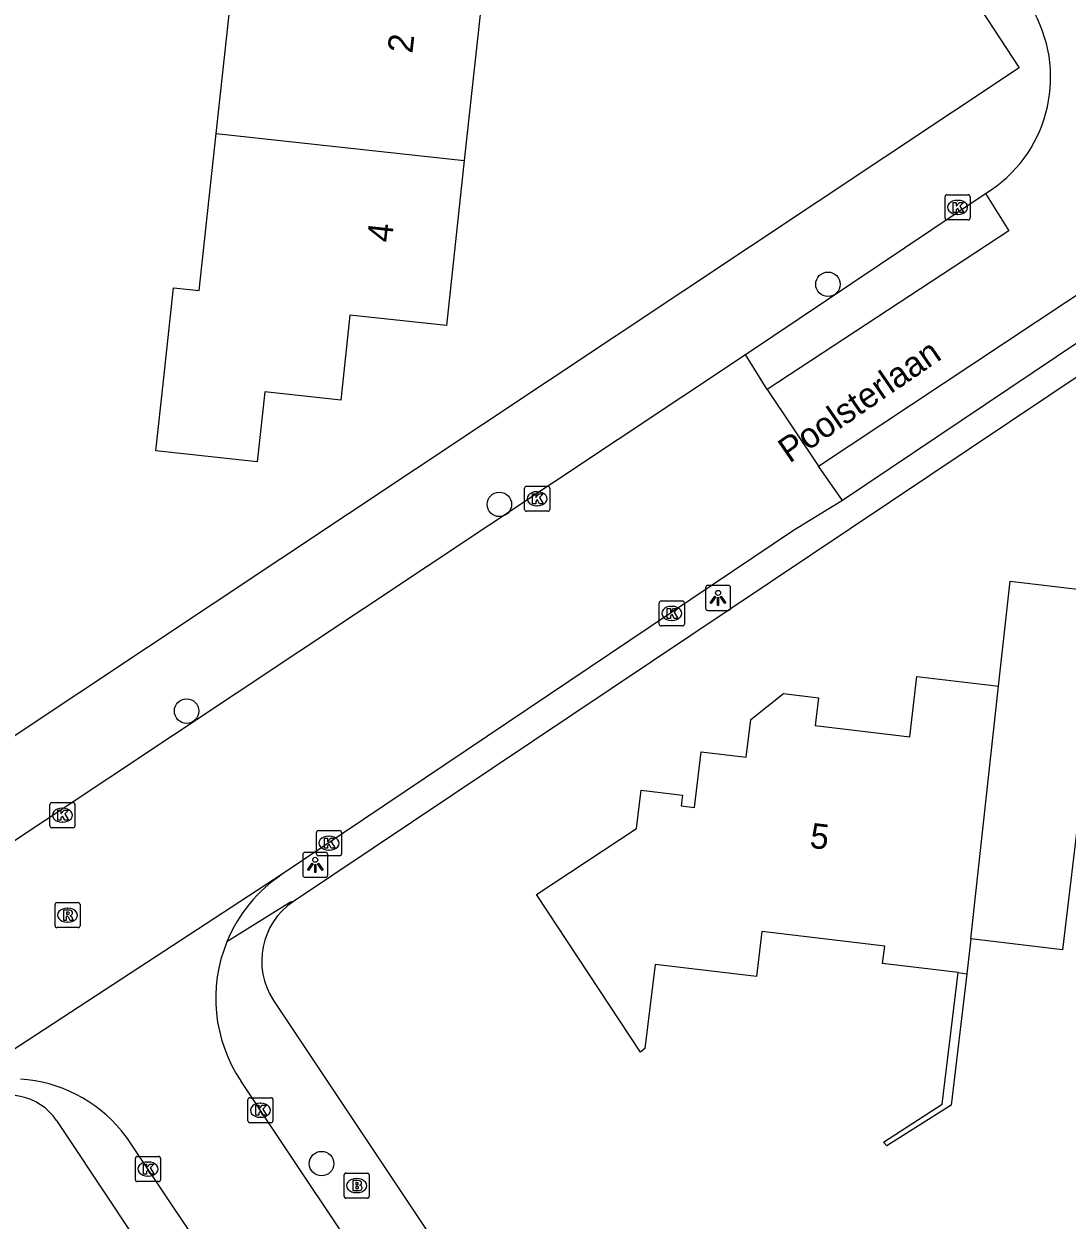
# Model space of a CAD drawing. Extents: x 162398 to 163643, y 386453 to 387397.
# Drawn here: x 163055.23 to 163096.85, y 386746.74 to 386794.48 of the extents above; entities that cross this region are included whole.
import ezdxf

# ---------------------------------------------------------------- set-up
doc = ezdxf.new("R2010")
doc.units = 0
for name, color, linetype in [('IMGEO_Boom', 7, 'Continuous'), ('IMGEO_Brandkraan', 7, 'Continuous'), ('IMGEO_Kolk', 7, 'Continuous'), ('IMGEO_Lichtpunt', 7, 'Continuous'), ('IMGEO_Muur', 7, 'Continuous'), ('IMGEO_Openbare_ruimte_label', 7, 'Continuous'), ('IMGEO_Pand', 7, 'Continuous'), ('IMGEO_Pand_nummerreeks', 7, 'Continuous'), ('IMGEO_Rijbaan_lokaal_gesloten', 7, 'Continuous'), ('IMGEO_Rijbaan_lokaal_open', 7, 'Continuous'), ('IMGEO_Rioolput', 7, 'Continuous'), ('IMGEO_Voetpad_open', 7, 'Continuous')]:
    doc.layers.add(name, color=color, linetype=linetype)

msp = doc.modelspace()

# ---------------------------------------------------------------- linework, layer by layer
at = {"layer": 'IMGEO_Boom'}
for centre in [(163087.31, 386784.089), (163074.198, 386775.307), (163061.721, 386767.055), (163067.103, 386748.994)]:
    msp.add_circle(centre, 0.489, dxfattribs=at)
at = {"layer": 'IMGEO_Brandkraan'}
for p, q in [((163068.004, 386747.688), (163068.004, 386748.54)), ((163068.079, 386748.614), (163068.931, 386748.614)), ((163068.492, 386748.394), (163068.517, 386748.394)), ((163069.005, 386748.54), (163069.005, 386747.688)), ((163068.515, 386747.834), (163068.49, 386747.834)), ((163068.931, 386747.614), (163068.079, 386747.614))]:
    msp.add_line(p, q, dxfattribs=at)
for points in [[(163068.004, 386747.688), (163068.004, 386748.54)], [(163068.079, 386748.614), (163068.931, 386748.614)], [(163068.352, 386748.314), (163068.352, 386747.914), (163068.565, 386747.914)], [(163068.583, 386748.314), (163068.352, 386748.314)], [(163068.531, 386748.233), (163068.477, 386748.233), (163068.477, 386748.157)], [(163069.005, 386748.54), (163069.005, 386747.688)], [(163068.477, 386748.157), (163068.53, 386748.157)], [(163068.539, 386748.081), (163068.477, 386748.081), (163068.477, 386748)], [(163068.477, 386748), (163068.539, 386748)], [(163068.931, 386747.614), (163068.079, 386747.614)]]:
    msp.add_lwpolyline(points, dxfattribs=at)
for centre, radius, start, end in [((163068.081, 386748.538), 0.0765, 91.552, 178.448), ((163068.081, 386748.538), 0.0765, 91.552, 178.448), ((163068.532, 386748.195), 0.0379, 267.8285, 90.9355), ((163068.587, 386748.169), 0.145, 59.4692, 91.5367), ((163068.612, 386748.216), 0.0922, 285.5137, 58.1501), ((163068.929, 386748.538), 0.0765, 1.552, 88.448), ((163068.929, 386748.538), 0.0765, 1.552, 88.448), ((163068.54, 386748.04), 0.0404, 269.8759, 90.5077), ((163068.571, 386748.165), 0.251, 268.6676, 293.5347), ((163068.617, 386748.024), 0.105, 301.3115, 78.989), ((163068.081, 386747.69), 0.0765, 181.552, 268.448), ((163068.081, 386747.69), 0.0765, 181.552, 268.448), ((163068.929, 386747.69), 0.0765, 271.552, 358.448), ((163068.929, 386747.69), 0.0765, 271.552, 358.448)]:
    msp.add_arc(centre, radius, start, end, dxfattribs=at)
for centre, major_axis, ratio, start_param, end_param in [((163068.491, 386748.114), (-0.387, 0.002), 0.722429, 4.712389, 7.853982), ((163068.516, 386748.114), (-0.39, 0.002), 0.717154, 1.570796, 4.712389)]:
    msp.add_ellipse(centre, major_axis=major_axis, ratio=ratio, start_param=start_param, end_param=end_param, dxfattribs=at)
at = {"layer": 'IMGEO_Kolk'}
for p, q in [((163091.982, 386786.735), (163091.982, 386787.587)), ((163092.057, 386787.661), (163092.909, 386787.661)), ((163092.47, 386787.441), (163092.495, 386787.441)), ((163092.983, 386787.587), (163092.983, 386786.735)), ((163092.909, 386786.661), (163092.057, 386786.661)), ((163092.493, 386786.881), (163092.468, 386786.881)), ((163075.205, 386775.104), (163075.205, 386775.956)), ((163075.28, 386776.03), (163076.132, 386776.03)), ((163076.206, 386775.956), (163076.206, 386775.104)), ((163075.693, 386775.81), (163075.718, 386775.81)), ((163076.132, 386775.03), (163075.28, 386775.03)), ((163075.716, 386775.25), (163075.691, 386775.25)), ((163080.579, 386770.528), (163080.579, 386771.38)), ((163080.654, 386771.454), (163081.506, 386771.454)), ((163081.067, 386771.234), (163081.092, 386771.234)), ((163081.58, 386771.38), (163081.58, 386770.528)), ((163081.09, 386770.674), (163081.065, 386770.674)), ((163081.506, 386770.454), (163080.654, 386770.454)), ((163056.264, 386762.476), (163056.264, 386763.328)), ((163056.339, 386763.402), (163057.191, 386763.402)), ((163056.752, 386763.182), (163056.777, 386763.182)), ((163057.265, 386763.328), (163057.265, 386762.476)), ((163056.775, 386762.622), (163056.75, 386762.622)), ((163057.191, 386762.402), (163056.339, 386762.402)), ((163066.901, 386761.357), (163066.901, 386762.209)), ((163066.976, 386762.283), (163067.828, 386762.283)), ((163067.902, 386762.209), (163067.902, 386761.357)), ((163067.389, 386762.063), (163067.414, 386762.063)), ((163067.828, 386761.283), (163066.976, 386761.283)), ((163067.412, 386761.503), (163067.387, 386761.503)), ((163064.239, 386751.623), (163065.091, 386751.623)), ((163064.164, 386750.697), (163064.164, 386751.549)), ((163064.652, 386751.403), (163064.677, 386751.403)), ((163065.165, 386751.549), (163065.165, 386750.697)), ((163065.091, 386750.623), (163064.239, 386750.623)), ((163064.675, 386750.843), (163064.65, 386750.843)), ((163059.677, 386748.351), (163059.677, 386749.203)), ((163059.752, 386749.277), (163060.604, 386749.277)), ((163060.678, 386749.203), (163060.678, 386748.351)), ((163060.165, 386749.057), (163060.19, 386749.057)), ((163060.604, 386748.277), (163059.752, 386748.277)), ((163060.188, 386748.497), (163060.163, 386748.497))]:
    msp.add_line(p, q, dxfattribs=at)
for points in [[(163091.982, 386786.735), (163091.982, 386787.587)], [(163092.057, 386787.661), (163092.909, 386787.661)], [(163092.983, 386787.587), (163092.983, 386786.735)], [(163092.303, 386787.361), (163092.426, 386787.361), (163092.426, 386787.21), (163092.556, 386787.361), (163092.72, 386787.361), (163092.574, 386787.21), (163092.727, 386786.961), (163092.575, 386786.961), (163092.49, 386787.125), (163092.426, 386787.058), (163092.426, 386786.961), (163092.303, 386786.961), (163092.303, 386787.361)], [(163092.909, 386786.661), (163092.057, 386786.661)], [(163075.205, 386775.104), (163075.205, 386775.956)], [(163075.28, 386776.03), (163076.132, 386776.03)], [(163076.206, 386775.956), (163076.206, 386775.104)], [(163075.526, 386775.73), (163075.649, 386775.73), (163075.649, 386775.579), (163075.779, 386775.73), (163075.943, 386775.73), (163075.797, 386775.579), (163075.95, 386775.33), (163075.798, 386775.33), (163075.713, 386775.494), (163075.649, 386775.427), (163075.649, 386775.33), (163075.526, 386775.33), (163075.526, 386775.73)], [(163076.132, 386775.03), (163075.28, 386775.03)], [(163080.579, 386770.528), (163080.579, 386771.38)], [(163080.654, 386771.454), (163081.506, 386771.454)], [(163080.9, 386771.154), (163081.023, 386771.154), (163081.023, 386771.003), (163081.153, 386771.154), (163081.317, 386771.154), (163081.171, 386771.003), (163081.324, 386770.754), (163081.172, 386770.754), (163081.087, 386770.918), (163081.023, 386770.851), (163081.023, 386770.754), (163080.9, 386770.754), (163080.9, 386771.154)], [(163081.58, 386771.38), (163081.58, 386770.528)], [(163081.506, 386770.454), (163080.654, 386770.454)], [(163056.264, 386762.476), (163056.264, 386763.328)], [(163056.339, 386763.402), (163057.191, 386763.402)], [(163056.585, 386763.102), (163056.708, 386763.102), (163056.708, 386762.951), (163056.838, 386763.102), (163057.002, 386763.102), (163056.856, 386762.951), (163057.009, 386762.702), (163056.857, 386762.702), (163056.772, 386762.866), (163056.708, 386762.799), (163056.708, 386762.702), (163056.585, 386762.702), (163056.585, 386763.102)], [(163057.265, 386763.328), (163057.265, 386762.476)], [(163057.191, 386762.402), (163056.339, 386762.402)], [(163066.901, 386761.357), (163066.901, 386762.209)], [(163066.976, 386762.283), (163067.828, 386762.283)], [(163067.902, 386762.209), (163067.902, 386761.357)], [(163067.222, 386761.983), (163067.345, 386761.983), (163067.345, 386761.832), (163067.475, 386761.983), (163067.639, 386761.983), (163067.493, 386761.832), (163067.646, 386761.583), (163067.494, 386761.583), (163067.409, 386761.747), (163067.345, 386761.68), (163067.345, 386761.583), (163067.222, 386761.583), (163067.222, 386761.983)], [(163067.828, 386761.283), (163066.976, 386761.283)], [(163064.239, 386751.623), (163065.091, 386751.623)], [(163064.164, 386750.697), (163064.164, 386751.549)], [(163064.485, 386751.323), (163064.608, 386751.323), (163064.608, 386751.172), (163064.738, 386751.323), (163064.902, 386751.323), (163064.756, 386751.172), (163064.909, 386750.923), (163064.757, 386750.923), (163064.672, 386751.087), (163064.608, 386751.02), (163064.608, 386750.923), (163064.485, 386750.923), (163064.485, 386751.323)], [(163065.165, 386751.549), (163065.165, 386750.697)], [(163065.091, 386750.623), (163064.239, 386750.623)], [(163059.677, 386748.351), (163059.677, 386749.203)], [(163059.752, 386749.277), (163060.604, 386749.277)], [(163060.678, 386749.203), (163060.678, 386748.351)], [(163059.998, 386748.977), (163060.121, 386748.977), (163060.121, 386748.826), (163060.251, 386748.977), (163060.415, 386748.977), (163060.269, 386748.826), (163060.422, 386748.577), (163060.27, 386748.577), (163060.185, 386748.741), (163060.121, 386748.674), (163060.121, 386748.577), (163059.998, 386748.577), (163059.998, 386748.977)], [(163060.604, 386748.277), (163059.752, 386748.277)]]:
    msp.add_lwpolyline(points, dxfattribs=at)
for centre, start, end in [((163092.059, 386787.585), 91.552, 178.448), ((163092.059, 386787.585), 91.552, 178.448), ((163092.907, 386787.585), 1.552, 88.448), ((163092.907, 386787.585), 1.552, 88.448), ((163092.059, 386786.737), 181.552, 268.448), ((163092.059, 386786.737), 181.552, 268.448), ((163092.907, 386786.737), 271.552, 358.448), ((163092.907, 386786.737), 271.552, 358.448), ((163075.282, 386775.954), 91.552, 178.448), ((163075.282, 386775.954), 91.552, 178.448), ((163076.13, 386775.954), 1.552, 88.448), ((163076.13, 386775.954), 1.552, 88.448), ((163075.282, 386775.106), 181.552, 268.448), ((163075.282, 386775.106), 181.552, 268.448), ((163076.13, 386775.106), 271.552, 358.448), ((163076.13, 386775.106), 271.552, 358.448), ((163080.656, 386771.378), 91.552, 178.448), ((163080.656, 386771.378), 91.552, 178.448), ((163081.504, 386771.378), 1.552, 88.448), ((163081.504, 386771.378), 1.552, 88.448), ((163080.656, 386770.53), 181.552, 268.448), ((163080.656, 386770.53), 181.552, 268.448), ((163081.504, 386770.53), 271.552, 358.448), ((163081.504, 386770.53), 271.552, 358.448), ((163056.341, 386763.326), 91.552, 178.448), ((163056.341, 386763.326), 91.552, 178.448), ((163057.189, 386763.326), 1.552, 88.448), ((163057.189, 386763.326), 1.552, 88.448), ((163056.341, 386762.478), 181.552, 268.448), ((163056.341, 386762.478), 181.552, 268.448), ((163057.189, 386762.478), 271.552, 358.448), ((163057.189, 386762.478), 271.552, 358.448), ((163066.978, 386762.207), 91.552, 178.448), ((163066.978, 386762.207), 91.552, 178.448), ((163067.826, 386762.207), 1.552, 88.448), ((163067.826, 386762.207), 1.552, 88.448), ((163066.978, 386761.359), 181.552, 268.448), ((163066.978, 386761.359), 181.552, 268.448), ((163067.826, 386761.359), 271.552, 358.448), ((163067.826, 386761.359), 271.552, 358.448), ((163064.241, 386751.547), 91.552, 178.448), ((163064.241, 386751.547), 91.552, 178.448), ((163065.089, 386751.547), 1.552, 88.448), ((163065.089, 386751.547), 1.552, 88.448), ((163064.241, 386750.699), 181.552, 268.448), ((163064.241, 386750.699), 181.552, 268.448), ((163065.089, 386750.699), 271.552, 358.448), ((163065.089, 386750.699), 271.552, 358.448), ((163059.754, 386749.201), 91.552, 178.448), ((163059.754, 386749.201), 91.552, 178.448), ((163060.602, 386749.201), 1.552, 88.448), ((163060.602, 386749.201), 1.552, 88.448), ((163059.754, 386748.353), 181.552, 268.448), ((163059.754, 386748.353), 181.552, 268.448), ((163060.602, 386748.353), 271.552, 358.448), ((163060.602, 386748.353), 271.552, 358.448)]:
    msp.add_arc(centre, 0.0765, start, end, dxfattribs=at)
for centre, major_axis, ratio, start_param, end_param in [((163092.469, 386787.161), (-0.387, 0.002), 0.722429, 4.712389, 7.853982), ((163092.494, 386787.161), (-0.39, 0.002), 0.717154, 1.570796, 4.712389), ((163075.692, 386775.53), (-0.387, 0.002), 0.722429, 4.712389, 7.853982), ((163075.717, 386775.53), (-0.39, 0.002), 0.717154, 1.570796, 4.712389), ((163081.066, 386770.954), (-0.387, 0.002), 0.722429, 4.712389, 7.853982), ((163081.091, 386770.954), (-0.39, 0.002), 0.717154, 1.570796, 4.712389), ((163056.751, 386762.902), (-0.387, 0.002), 0.722429, 4.712389, 7.853982), ((163056.776, 386762.902), (-0.39, 0.002), 0.717154, 1.570796, 4.712389), ((163067.388, 386761.783), (-0.387, 0.002), 0.722429, 4.712389, 7.853982), ((163067.413, 386761.783), (-0.39, 0.002), 0.717154, 1.570796, 4.712389), ((163064.651, 386751.123), (-0.387, 0.002), 0.722429, 4.712389, 7.853982), ((163064.676, 386751.123), (-0.39, 0.002), 0.717154, 1.570796, 4.712389), ((163060.164, 386748.777), (-0.387, 0.002), 0.722429, 4.712389, 7.853982), ((163060.189, 386748.777), (-0.39, 0.002), 0.717154, 1.570796, 4.712389)]:
    msp.add_ellipse(centre, major_axis=major_axis, ratio=ratio, start_param=start_param, end_param=end_param, dxfattribs=at)
at = {"layer": 'IMGEO_Lichtpunt'}
for p, q in [((163082.426, 386771.976), (163082.426, 386771.169)), ((163082.426, 386771.976), (163082.426, 386771.169)), ((163083.328, 386772.071), (163082.52, 386772.071)), ((163083.328, 386772.071), (163082.52, 386772.071)), ((163083.422, 386771.169), (163083.422, 386771.976)), ((163083.422, 386771.169), (163083.422, 386771.976)), ((163082.52, 386771.075), (163083.328, 386771.075)), ((163082.52, 386771.075), (163083.328, 386771.075)), ((163066.354, 386761.321), (163066.354, 386760.514)), ((163066.354, 386761.321), (163066.354, 386760.514)), ((163067.256, 386761.416), (163066.448, 386761.416)), ((163067.256, 386761.416), (163066.448, 386761.416)), ((163067.35, 386760.514), (163067.35, 386761.321)), ((163067.35, 386760.514), (163067.35, 386761.321)), ((163066.448, 386760.42), (163067.256, 386760.42)), ((163066.448, 386760.42), (163067.256, 386760.42))]:
    msp.add_line(p, q, dxfattribs=at)
for points in [[(163082.8, 386771.64), (163082.839, 386771.612), (163082.651, 386771.35), (163082.613, 386771.377), (163082.8, 386771.64)], [(163083.012, 386771.612), (163083.05, 386771.639), (163083.237, 386771.377), (163083.198, 386771.349), (163083.012, 386771.612)], [(163082.902, 386771.592), (163082.949, 386771.592), (163082.949, 386771.27), (163082.902, 386771.27), (163082.902, 386771.592)], [(163066.728, 386760.985), (163066.767, 386760.957), (163066.579, 386760.695), (163066.541, 386760.722), (163066.728, 386760.985)], [(163066.83, 386760.937), (163066.877, 386760.937), (163066.877, 386760.615), (163066.83, 386760.615), (163066.83, 386760.937)], [(163066.94, 386760.957), (163066.978, 386760.984), (163067.165, 386760.722), (163067.126, 386760.694), (163066.94, 386760.957)]]:
    msp.add_lwpolyline(points, dxfattribs=at)
for centre in [(163082.925, 386771.774), (163066.853, 386761.119)]:
    msp.add_circle(centre, 0.0994, dxfattribs=at)
for centre, start, end in [((163082.52, 386771.976), 90, 180), ((163082.52, 386771.976), 90, 180), ((163083.328, 386771.976), 0, 90), ((163083.328, 386771.976), 0, 90), ((163082.52, 386771.169), 180, 270), ((163082.52, 386771.169), 180, 270), ((163083.328, 386771.169), 270, 0), ((163083.328, 386771.169), 270, 360), ((163066.448, 386761.321), 90, 180), ((163066.448, 386761.321), 90, 180), ((163067.256, 386761.321), 0, 90), ((163067.256, 386761.321), 0, 90), ((163066.448, 386760.514), 180, 270), ((163066.448, 386760.514), 180, 270), ((163067.256, 386760.514), 270, 0), ((163067.256, 386760.514), 270, 360)]:
    msp.add_arc(centre, 0.0946, start, end, dxfattribs=at)
at = {"layer": 'IMGEO_Muur'}
msp.add_lwpolyline([(163092.848, 386756.574), (163092.221, 386751.327), (163089.656, 386749.699), (163089.531, 386749.856), (163091.873, 386751.371), (163092.499, 386756.616)], dxfattribs=at)
at = {"layer": 'IMGEO_Pand'}
for points in [[(163062.9, 386790.106), (163063.658, 386797.073), (163062.183, 386797.234), (163062.587, 386800.949), (163065.941, 386800.584), (163071.468, 386799.982), (163071.59, 386801.104), (163073.363, 386800.911), (163078.333, 386800.37), (163077.975, 386797.081), (163073.726, 386797.543), (163072.8, 386789.031)], [(163072.8, 386789.031), (163072.083, 386782.446), (163068.239, 386782.864), (163067.869, 386779.463), (163064.845, 386779.792), (163064.541, 386777.006), (163060.493, 386777.447), (163060.796, 386780.233), (163061.201, 386783.951), (163062.218, 386783.841), (163062.9, 386790.106)], [(163062.9, 386790.106), (163072.8, 386789.031)], [(163106.653, 386775.013), (163106.471, 386773.435), (163105.449, 386764.595), (163101.649, 386765.034), (163101.577, 386764.413), (163097.541, 386764.869), (163096.663, 386757.522), (163093.013, 386757.959)], [(163094.119, 386768.051), (163094.578, 386772.239), (163098.281, 386771.797), (163098.656, 386774.94)], [(163092.499, 386756.616), (163089.491, 386756.976), (163089.574, 386757.666), (163084.667, 386758.252), (163084.452, 386756.458), (163080.41, 386756.941), (163080.009, 386753.583), (163079.836, 386753.446), (163075.679, 386759.73), (163079.668, 386762.37), (163079.851, 386763.903), (163081.509, 386763.705), (163081.458, 386763.276), (163081.985, 386763.213), (163082.25, 386765.425), (163084.046, 386765.21), (163084.226, 386766.719), (163085.541, 386767.753), (163086.93, 386767.587), (163086.798, 386766.485), (163090.575, 386766.034), (163090.862, 386768.441), (163093.794, 386768.09), (163094.119, 386768.051)], [(163093.013, 386757.959), (163094.119, 386768.051)], [(163093.013, 386757.959), (163092.848, 386756.574)], [(163092.499, 386756.616), (163092.848, 386756.574)]]:
    msp.add_lwpolyline(points, dxfattribs=at)
at = {"layer": 'IMGEO_Rijbaan_lokaal_gesloten'}
for points in [[(163018.704, 386737.897), (163020.532, 386739.148), (163021.049, 386739.492), (163022.823, 386740.671), (163027.385, 386743.673), (163037.12, 386750.107), (163044.946, 386755.247), (163053.527, 386761.018), (163084.016, 386781.282)], [(163084.887, 386779.893), (163084.016, 386781.282)], [(163087.891, 386775.462), (163086.931, 386776.836)], [(163087.891, 386775.462), (163085.934, 386774.259), (163065.539, 386760.542)], [(163065.539, 386760.542), (163051.663, 386751.486)]]:
    msp.add_lwpolyline(points, dxfattribs=at)
at = {"layer": 'IMGEO_Rijbaan_lokaal_open'}
for points in [[(163086.931, 386776.836), (163111.717, 386793.28)], [(163112.536, 386792.008), (163087.891, 386775.462)], [(163084.016, 386781.282), (163093.6, 386787.714)], [(163093.6, 386787.714), (163094.527, 386786.223), (163084.887, 386779.893)], [(163084.887, 386779.893), (163086.931, 386776.836)], [(163083.743, 386722.54), (163065.412, 386750), (163063.882, 386752.292)], [(163062.126, 386745.866), (163061.185, 386747.272), (163059.355, 386750), (163059.121, 386750.304)]]:
    msp.add_lwpolyline(points, dxfattribs=at)
for centre, radius, start, end in [((163090.757, 386792.349), 5.437, 301.522, 28.2464), ((163068.818, 386755.596), 5.935, 123.5452, 157.6653), ((163068.828, 386755.591), 5.946, 157.6605, 213.7015), ((163054.72, 386746.67), 5.708, 39.5432, 86.3086)]:
    msp.add_arc(centre, radius, start, end, dxfattribs=at)
at = {"layer": 'IMGEO_Rioolput'}
for p, q in [((163056.469, 386758.485), (163056.469, 386759.337)), ((163056.544, 386759.411), (163057.396, 386759.411)), ((163057.47, 386759.337), (163057.47, 386758.485)), ((163056.957, 386759.191), (163056.982, 386759.191)), ((163057.396, 386758.411), (163056.544, 386758.411)), ((163056.98, 386758.631), (163056.955, 386758.631))]:
    msp.add_line(p, q, dxfattribs=at)
for points in [[(163056.469, 386758.485), (163056.469, 386759.337)], [(163056.544, 386759.411), (163057.396, 386759.411)], [(163057.47, 386759.337), (163057.47, 386758.485)], [(163057.058, 386759.109), (163056.806, 386759.111), (163056.806, 386758.711)], [(163056.806, 386758.711), (163056.93, 386758.711), (163056.93, 386758.873), (163056.941, 386758.873)], [(163056.984, 386759.03), (163056.93, 386759.03), (163056.93, 386758.949)], [(163056.93, 386758.949), (163056.982, 386758.949)], [(163056.988, 386758.844), (163057.059, 386758.711), (163057.199, 386758.711), (163057.134, 386758.837)], [(163057.396, 386758.411), (163056.544, 386758.411)]]:
    msp.add_lwpolyline(points, dxfattribs=at)
for centre, radius, start, end in [((163056.546, 386759.335), 0.0765, 91.552, 178.448), ((163056.546, 386759.335), 0.0765, 91.552, 178.448), ((163057.394, 386759.335), 0.0765, 1.552, 88.448), ((163057.394, 386759.335), 0.0765, 1.552, 88.448), ((163056.94, 386758.82), 0.0533, 26.0293, 88.6989), ((163056.966, 386759.138), 0.19, 274.7715, 282.9687), ((163056.99, 386758.934), 0.0964, 77.0061, 93.1865), ((163057.004, 386758.991), 0.0378, 276.6634, 79.6772), ((163057.057, 386758.999), 0.109, 350.3612, 89.416), ((163057.055, 386758.999), 0.112, 277.5842, 350.9817), ((163057.039, 386758.784), 0.108, 29.5134, 73.7905), ((163056.546, 386758.487), 0.0765, 181.552, 268.448), ((163056.546, 386758.487), 0.0765, 181.552, 268.448), ((163057.394, 386758.487), 0.0765, 271.552, 358.448), ((163057.394, 386758.487), 0.0765, 271.552, 358.448)]:
    msp.add_arc(centre, radius, start, end, dxfattribs=at)
for centre, major_axis, ratio, start_param, end_param in [((163056.956, 386758.911), (-0.387, 0.002), 0.722429, 4.712389, 7.853982), ((163056.981, 386758.911), (-0.39, 0.002), 0.717154, 1.570796, 4.712389)]:
    msp.add_ellipse(centre, major_axis=major_axis, ratio=ratio, start_param=start_param, end_param=end_param, dxfattribs=at)
at = {"layer": 'IMGEO_Voetpad_open'}
for points in [[(163146.898, 386813.664), (163065.982, 386759.453)], [(163090.874, 386798.95), (163094.938, 386792.726), (163030.691, 386750), (163014.944, 386739.528)], [(163065.982, 386759.453), (163065.864, 386759.423), (163063.329, 386757.851)], [(163065.193, 386755.51), (163068.861, 386750), (163085.772, 386724.593)], [(163056.534, 386750.711), (163057.006, 386750), (163062.275, 386742.065)]]:
    msp.add_lwpolyline(points, dxfattribs=at)
for centre, radius, start, end in [((163067.559, 386757.087), 2.844, 123.6894, 213.6795), ((163054.648, 386749.448), 2.27, 33.8084, 123.6278)]:
    msp.add_arc(centre, radius, start, end, dxfattribs=at)

# ---------------------------------------------------------------- texts
at = {"layer": 'IMGEO_Openbare_ruimte_label'}
msp.add_text('Poolsterlaan', height=1, rotation=34.4525, dxfattribs=at).set_placement((163085.774, 386776.928))
at = {"layer": 'IMGEO_Pand_nummerreeks'}
for s, rotation, p in [('2', 83.7893, (163070.728, 386793.285)), ('4', 83.7859, (163069.907, 386785.737)), ('5', 353.1761, (163086.553, 386761.606))]:
    msp.add_text(s, height=1, rotation=rotation, dxfattribs=at).set_placement(p)

doc.saveas('drawing.dxf')
